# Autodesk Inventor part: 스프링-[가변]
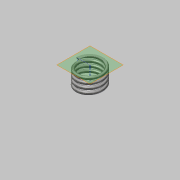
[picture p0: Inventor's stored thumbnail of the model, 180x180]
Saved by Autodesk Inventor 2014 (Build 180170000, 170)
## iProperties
Created: 2015-05
Part Number: 스프링-[가변]
Material: 강철, 탄소
Document SubType Name: Modeling
Designer: Administrator
Density: 7.87 g/cm^3
Appearance: 반연마
Mass: 4.78745 g
Surface Area: 12.524 cm^2
Volume: 0.608316 cm^3
Author: Administrator
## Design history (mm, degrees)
sketch "스케치1"
  geometry: L1 (0, 0)-(-8, 0); L2 (-8, 0)-(-8, 11.5); L3 (-8, 11.5)-(0, 11.5); L4 (0, 11.5)-(0, 0); C1 r 1 at (-8, 0)
  constraints: 8 end point, 2 parallel, 1 centre point, 1 coincident, 1 horizontal, 1 perpendicular
  dimensions: "d0" = 16 diameter of L2 L4; "d1" = 11.50049 distance between parallel lines of L3 L1 (derived); "d2" = 2 diameter of C1
feature "코일1" pitch "d3" = 10; turns "d5" = 4; dims "d4" = 11.50049 (= d1), "d6" = 0, angle "d7" = 90 deg, angle "d8" = 90 deg, "d9" = 0, "d10" = 0
sketch "스케치2"
  geometry: L1 (9, 0)-(7, 0) reference; 1 further point
  constraints: 1 horizontal alignment
extrude "돌출1" cut sketch "스케치2" stored distance "d11" = 10; taper "d12" = 0 deg
node "작업 평면1"
sketch "스케치3"
  geometry: L1 (-9, 0)-(-7, 0) reference; 1 further point
  constraints: 1 horizontal alignment
extrude "돌출2" cut sketch "스케치3" stored distance "d13" = 10; taper "d14" = 0 deg
node "솔리드1"
node "절단 모서리 투영1"
node "절단 모서리 투영2"
